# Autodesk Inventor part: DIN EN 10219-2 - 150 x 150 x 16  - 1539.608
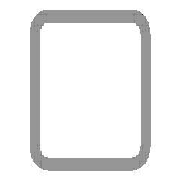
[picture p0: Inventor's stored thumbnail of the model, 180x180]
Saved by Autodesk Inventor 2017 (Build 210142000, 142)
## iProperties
Created: 2017-11
Part Number: DIN EN 10219-2 - 150 x 150 x 16  - 1539.608
Material: Steel, Mild
Description: Cold formed welded structural hollow sections of non-alloy and fine grain structural steel
Document SubType Name: Modeling
Standard: DIN
Designer: iusti
Standard Revision: 2006-07
Standards Organization: DIN
Language: en-US
Size Designation: 150 x 150 x 16
Categories: <MemberInstance><Categories><Category DisplayName="Structural Shapes" InternalName="089c4875-fa83-4c05-b084-43b9cc11f5ed" Mnemonic="GRDR"><CategoryParameter Dis
Stock Number: 150 x 150 x 16
Mass: 90369.3 g
Surface Area: 14539.6 cm^2
Volume: 11512 cm^3
Density: 7.85 g/cm^3
Appearance: Semi-Polished
IsCustomPart: 1
G_W: 150.000 mm
G_H: 150.000 mm
G_L: 1539.608 mm
+DD82D223-1000-45B8-A0F4-80F9EFDCC45E+CUTDETAIL2: Cut
_CCFamilyMember: 76
_CCFamilyDisplayName: DIN EN 10219-2 (Square Hollow Section - Cold Formed) - Cold formed welded structural hollow sections of non-alloy and fine grain structural steel
_FrameMemberDoc: Frame Member File
_Version: 15.0.0
_GetPNFromCC: 1
Author: iusti
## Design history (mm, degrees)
node "Start plane"
node "End plane"
sketch "Sketch"
  geometry: L1 (-75, -27)-(-75, 27); L2 (-27, 75)-(27, 75); L3 (75, 27)-(75, -27); L4 (27, -75)-(-27, -75); L5 (-27, 59)-(27, 59); L6 (59, 27)-(59, -27); L7 (27, -59)-(-27, -59); L8 (-59, -27)-(-59, 27); L9 (0, 118.918)-(0, -118.918) reference; L10 (-118.918, 0)-(118.918, 0) reference; A1 r 48 centre (-27, -27) between (-75, -27) and (-27, -75); A2 r 48 centre (-27, 27) between (-27, 75) and (-75, 27); A3 r 48 centre (27, 27) between (75, 27) and (27, 75); A4 r 48 centre (27, -27) between (27, -75) and (75, -27); A5 r 32 centre (-27, 27) between (-27, 59) and (-59, 27); A6 r 32 centre (27, 27) between (59, 27) and (27, 59); A7 r 32 centre (27, -27) between (27, -59) and (59, -27); A8 r 32 centre (-27, -27) between (-59, -27) and (-27, -59)
  constraints: 16 end point, 16 point on circle, 8 centre point, 8 tangent, 4 parallel, 3 equal radius, 2 perpendicular, 7 other
  dimensions: "d7" = 48 radius of A1 (= G_IR); "d10" = 150 distance between parallel lines of L2 L4 (= G_H); "d11" = 150 distance between parallel lines of L1 L3 (= G_W); "d12" = 16 distance between parallel lines of L3 L6 (= G_T); "d15" = 75 distance between parallel lines of L2 L10 (= 0.5 x d10); "d16" = 75 distance between parallel lines of L9 L3 (= 0.5 x d11)
extrude "Body" new body sketch "Sketch" stored distance "d3" = 1539.60835 (= G_L); taper "d4" = 0 deg
node "Driven Length"
  sketch "Sketch3"
    geometry: L1 (0, 0)-(10, 0) reference
    constraints: 2 end point, 1 horizontal
  workplane "Work Plane3"
  sketch "Sketch4"
    geometry: L1 (-2, 75)-(12, 75) reference; L2 (-2, 1614.608)-(12, 1614.608) reference
    dimensions: "d18" = 1539.60835 distance between parallel lines of L1 L2 (derived)
workplane "Work Plane5"
split "Split2"
body "Solid1"
other parameters: "G_W" = 150 [user parameter; used in 1 equation term], "G_H" = 150 [user parameter; used in 1 equation term], "G_T" = 16 [user parameter; used in 1 equation term], "G_IR" = 48 [user parameter; used in 1 equation term], "G_L" = 1539.60835 (= d18) [user parameter; used in 1 equation term], "G_OFFSET_START" = -75 [user parameter; used in 1 equation term], "G_OFFSET_END" = 0 [user parameter; used in 1 equation term], "d13" = 75 (= -G_OFFSET_START), "d14" = 1614.60835 (= G_OFFSET_END + B_L), "B_L" = 1614.60835 [user parameter; used in 1 equation term], "d17" = 90 deg
